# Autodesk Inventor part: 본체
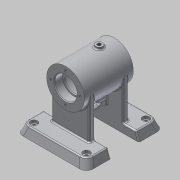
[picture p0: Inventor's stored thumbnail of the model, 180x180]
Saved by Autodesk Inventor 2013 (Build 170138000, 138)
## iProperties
Created: 2016-07
Part Number: 본체
Material: 알루미늄 6061
Document SubType Name: Modeling
Designer: Administrator
Density: 2.71 g/cm^3
Mass: 500.66 g
Surface Area: 530.533 cm^2
Volume: 184.745 cm^3
Author: Administrator
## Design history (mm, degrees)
sketch "스케치2"
  geometry: L1 (0, 0)-(70, 0); L2 (0, 27)-(70, 27); L3 (0, 27)-(0, 16); L4 (0, 16)-(12, 16); L5 (12, 16)-(12, 14); L6 (12, 14)-(14, 14); L7 (14, 14)-(14, 22); L8 (14, 22)-(56, 22); L9 (56, 22)-(56, 14); L10 (56, 14)-(58, 14); L11 (58, 14)-(58, 16); L12 (58, 16)-(70, 16); L13 (70, 16)-(70, 27)
  constraints: 26 end point, 6 parallel, 6 perpendicular, 1 horizontal, 1 vertical
  dimensions: "d0" = 0 distance from line of L3 L1.start; "d1" = 32 diameter of L4 L1; "d2" = 12 distance between parallel lines of L5 L3; "d3" = 54 diameter of L2 L1; "d4" = 28 diameter of L6 L1; "d5" = 42 distance between parallel lines of L9 L7; "d6" = 44 diameter of L8 L1; "d7" = 2 distance of L5.end L6.end; "d8" = 70 distance of L2.start L2.end; "d9" = 32 diameter of L12 L1; "d10" = 2 distance of L9.end L10.end; "d11" = 28 diameter of L10 L1
revolve "회전1" sketch "스케치2" stored, may be unused: angle "d12" = 90 deg
node "작업 평면1"
sketch "스케치3"
  geometry: L1 (27, 70)-(-27, 70) reference; L2 (27, 0)-(-27, 0) reference; L3 (27, 0)-(-27, 0) reference; L4 (-25.21, 35)-(27.411, 35); L5 (-50, 90)-(50, 90); L6 (50, 90)-(50, 55); L7 (50, 55)-(-50, 55); L8 (-50, 55)-(-50, 90); L9 (0, 70)-(0, 0); L10 (-50, 15)-(50, 15); L11 (50, 15)-(50, -20); L12 (50, -20)-(-50, -20); L13 (-50, -20)-(-50, 15); L14 (-4, 55)-(-4, 15); L15 (4, 15)-(4, 55)
  constraints: 24 end point, 6 parallel, 4 perpendicular, 4 point on line, 2 horizontal, 1 midpoint
  dimensions: "d14" = 35 distance between parallel lines of L4 L1; "d16" = 100 distance between parallel lines of L6 L8; "d18" = 50 distance between parallel lines of L9 L8; "d19" = 35 distance between parallel lines of L5 L7; "d20" = 55 distance between parallel lines of L4 L5; "d21" = 55 distance between parallel lines of L12 L4; "d22" = 35 distance between parallel lines of L12 L10; "d23" = 100 distance between parallel lines of L13 L11; "d24" = 50 distance between parallel lines of L9 L13; "d25" = 8 distance between parallel lines of L15 L14; "d26" = 4 distance between parallel lines of L9 L14 (= 0.5 x d25)
extrude "돌출1" join sketch "스케치3" distance "d27" = 12; taper "d28" = 0 deg
sketch "스케치4"
  geometry: L1 (0, 0)-(100, 0) reference; L2 (100, 0)-(100, 12) reference; L3 (0, 12)-(100, 12) reference; L4 (0, 0)-(0, 12) reference; L5 (95.632, 12)-(100, 0); L6 (4.368, 12)-(0, 0); 1 further point
  constraints: 4 end point, 2 point on line
  dimensions: "d29" = 110 deg angle of L1 L5; "d30" = 110 deg angle of L1 L6
extrude "돌출2" cut sketch "스케치4" stored distance "d31" = 12; taper "d32" = 0 deg
node "작업 평면2"
sketch "스케치5"
  geometry: L1 (15, -58)-(15, -70) reference; L2 (-20, -58)-(15, -58) reference; L3 (-20, -70)-(-20, -58) reference; L4 (-20, -70)-(15, -70) reference; L5 (55, -70)-(55, -58) reference; L6 (55, -70)-(90, -70) reference; L7 (90, -58)-(90, -70) reference; L8 (55, -58)-(90, -58) reference; L9 (-20, -70)-(-15.632, -58); L10 (90, -70)-(85.632, -58); 1 further point
  constraints: 4 end point, 2 point on line
  dimensions: "d34" = 110 deg angle of L4 L9; "d35" = 110 deg angle of L6 L10
extrude "돌출3" cut sketch "스케치5" stored distance "d36" = 12; taper "d37" = 0 deg
sketch "스케치6"
  geometry: L1 (45.632, 15)-(4, 15) reference; L2 (4, 55)-(45.632, 55) reference; L3 (-45.632, 55)-(-4, 55) reference; L4 (-4, 55)-(-4, 15) reference; L5 (-4, 15)-(-45.632, 15) reference; L6 (27, 15)-(27, 7); L7 (27, 7)-(-27, 7); L8 (-27, 7)-(-27, 15); L9 (27, 55)-(27, 63); L10 (27, 63)-(-27, 63); L11 (-27, 63)-(-27, 55); L12 (0, 15)-(0, 55); L13 (-4, 15)-(-4, 55); L14 (4, 55)-(4, 15); L15 (-27, 15)-(-4, 15); L16 (4, 15)-(27, 15); L17 (4, 55)-(27, 55); L18 (-4, 55)-(-27, 55); 1 further point
  constraints: 26 end point, 5 collinear, 2 parallel, 2 point on line, 1 perpendicular
  dimensions: "d42" = 54 distance between parallel lines of L6 L8; "d48" = 54 distance between parallel lines of L9 L11; "d49" = 4 distance between parallel lines of L12 L4; "d50" = 27 distance from line of point (0, 0) L8; "d51" = 27 distance between parallel lines of L12 L11; "d52" = 8 distance between parallel lines of L2 L10; "d54" = 8 distance between parallel lines of L15 L7; "d55" = 8 distance of L6.start L6.end; "d56" = 0 distance from line of L15 L12.start; "d57" = 0 distance from line of L12.end L3
extrude "돌출4" join sketch "스케치6" stored distance "d58" = 12; taper "d59" = 0 deg
sketch "스케치7"
  geometry: L1 (0, 0)-(0, 40) reference; L2 (-22.298, 0)-(-22.298, 40); L3 (-43.298, 0)-(-43.298, 40) reference; L4 (-22.298, 0)-(0, 0); L5 (0, 40)-(-22.298, 40); L6 (0, 40)-(0, 0); 1 further point
  constraints: 8 end point, 2 equal length, 1 perpendicular
  dimensions: "d62" = 21 distance between parallel lines of L2 L3
extrude "돌출5" cut sketch "스케치7" stored distance "d63" = 12; taper "d64" = 0 deg
sketch "스케치8"
  geometry: L1 (21, 0)-(21, 40) reference; L2 (0, 0)-(0, 40) reference; L3 (21, 0)-(0, 0) reference; L4 (11.298, 8.5)-(11.298, 31.5); L5 (43.298, 40)-(43.298, 75) reference; L6 (0, 20)-(21, 20); L7 (0.298, -15)-(-53.702, -15) reference; L8 (7.798, 12)-(7.798, 28); L9 (14.798, 12)-(14.798, 28); A1 r 3.5 centre (11.298, 12) between (7.798, 12) and (14.798, 12); A2 r 3.5 centre (11.298, 28) between (14.798, 28) and (7.798, 28); 1 further point
  constraints: 8 end point, 4 point on circle, 4 tangent, 2 centre point, 2 midpoint, 2 perpendicular, 2 point on line
  dimensions: "d65" = 7 diameter of A1; "d67" = 7 diameter of A2; "d69" = 32 distance between parallel lines of L5 L4; "d70" = 35 distance between parallel lines of L6 L7; "d71" = 23 distance of L4.start L4.end; "d72" = 11.5 distance from line of L6 L4.start (= 0.5 x d71); "d73" = 23 dimension on A2 A1; "d74" = 11.5 dimension on A1 L6
extrude "돌출6" cut sketch "스케치8" stored distance "d75" = 12; taper "d76" = 0 deg
node "작업 평면3"
sketch "스케치9"
  geometry: L1 (0, 0)-(15.898, -25.441); L2 (0, 0)-(0, -14)
  constraints: 4 end point, 1 vertical, 1 vertical alignment, 1 other
  dimensions: "d78" = 30 distance of L1.start L1.end; "d79" = 32 deg angle of L2 L1
node "작업 평면4"
sketch "스케치10"
  geometry: L1 (-8, -14.89)-(8, -14.89) reference; L2 (-20, 7.963)-(-20, -7.838) reference; C1 r 6 at (0, 0.063); 3 further points
  constraints: 2 midpoint, 1 centre point, 1 horizontal alignment, 1 vertical alignment
  dimensions: "d80" = 12 diameter of C1
extrude "돌출7" join sketch "스케치10" stored distance "d82" = 12; taper "d83" = 0 deg
node "작업 평면6"
sketch "스케치11"
  geometry: L1 (27, 70)-(-27, 70) reference; C1 r 5 at (0, 48); 1 further point
  constraints: 1 centre point, 1 vertical alignment
  dimensions: "d85" = 10 diameter of C1; "d87" = 22 distance from line of L1 C1.centre
extrude "돌출8" join sketch "스케치11" stored distance "d88" = 12; taper "d89" = 0 deg
sketch "스케치12"
  geometry: L1 (-27, 55)-(-27, 63) reference; L2 (-27, 63)-(27, 63) reference; L3 (27, 63)-(27, 55) reference; L4 (27, 55)-(45.632, 55) reference; L5 (45.632, 55)-(45.632, 85.632) reference; L6 (45.632, 85.632)-(-45.632, 85.632) reference; L7 (-45.632, 85.632)-(-45.632, 55) reference; L8 (-45.632, 55)-(-27, 55) reference; L9 (-50, 15)-(-50, -20) reference; L10 (-50, -20)-(50, -20) reference; C1 r 5 at (-37.5, -7.5); 1 further point
  constraints: 1 centre point
  dimensions: "d90" = 10 diameter of C1; "d92" = 12.5 distance from line of L9 C1.centre; "d93" = 12.5 distance from line of L10 C1.centre
extrude "돌출9" cut sketch "스케치12" distance "d94" = 4; taper "d95" = 0 deg
sketch "스케치13"
  geometry: C1 r 5 at (0, 0) reference; C2 r 3 at (0, 0); 1 further point
  constraints: 1 centre point, 1 coincident
  dimensions: "d96" = 6 diameter of C2
extrude "돌출10" cut sketch "스케치13" stored distance "d98" = 4; taper "d99" = 0 deg
fillet "모깎기1" dims "d106" = 10
fillet "모깎기2" dims "d107" = 2
fillet "모깎기3" dims "d108" = 2
fillet "모깎기4" dims "d109" = 2
chamfer "모따기1" distance "d110" = 1; stored, may be unused: second distance "d111" = 2, angle "d112" = 110 deg
fillet "모깎기5" dims "d113" = 0.3
fillet "모깎기6" dims "d114" = 3
fillet "모깎기7" dims "d115" = 2
fillet "모깎기8" dims "d116" = 2
fillet "모깎기9" dims "d117" = 2
fillet "모깎기10" dims "d118" = 2
fillet "모깎기11" dims "d119" = 2
sketch "스케치14"
  geometry: C1 r 6 at (0, 0) reference; C2 r 3 at (0, 0); 1 further point
  constraints: 1 centre point, 1 coincident
  dimensions: "d120" = 6 diameter of C2
hole "구멍1" sketch "스케치14" at (0, 0) diameter "d122" = 5.188; stored, may be unused: countersink angle "d126" = 90 deg, drill point angle "d128" = 118 deg; dims "d123" = 6, "d124" = 4, "d125" = 2, "d127" = 8
sketch "스케치15"
  geometry: C1 r 5 at (0, 0) reference; C2 r 3 at (0, 0); 1 further point
  constraints: 1 centre point, 1 coincident
  dimensions: "d129" = 6 diameter of C2
hole "구멍2" sketch "스케치15" at (0, 0) diameter "d131" = 5.188; stored, may be unused: countersink angle "d135" = 90 deg, drill point angle "d137" = 118 deg; dims "d132" = 6, "d133" = 4, "d134" = 2, "d136" = 8
node "작업 평면7"
sketch "스케치16"
  geometry: L1 (-20.739, 1.26)-(20.739, 1.26); L2 (20.739, 1.26)-(20.739, -1.26); L3 (20.739, -1.26)-(-20.739, -1.26); L4 (-20.739, -1.26)-(-20.739, 1.26); L5 (-20.739, 0)-(20.739, 0); L6 (0, 1.26)-(0, -1.26); L7 (8, -32.5)-(-8, -32.5) reference; 3 further points
  constraints: 6 midpoint, 4 end point, 1 horizontal, 1 vertical alignment, 2 other
  dimensions: "d138" = 0 distance from line of point (35, 0) L5
feature "엠보싱1" sketch "스케치16" dims "d139" = 0.5, "d140" = 0
sketch "스케치17" dims "d141" = 42
  geometry: C1 r 27 at (0, 0) reference; C2 r 17 at (0, 0) reference; C3 r 2 at (0, 21); 1 further point
  constraints: 2 vertical alignment, 1 centre point, 1 coincident, 2 other
  dimensions: "d143" = 4 diameter of C3
hole "구멍3" sketch "스케치17" at (0, 21) diameter "d144" = 3.242; stored, may be unused: countersink angle "d148" = 82 deg, drill point angle "d150" = 118 deg; dims "d145" = 8, "d146" = 3.023, "d147" = 2, "d149" = 10
sketch "스케치18" dims "d154" = 42
  geometry: C1 r 27 at (0, 0) reference; C2 r 17 at (0, 0) reference; C3 r 2 at (0, -21); 1 further point
  constraints: 2 vertical alignment, 1 centre point, 1 coincident, 2 other
  dimensions: "d156" = 4 diameter of C3
hole "구멍4" sketch "스케치18" at (0, -21) diameter "d157" = 3.242; stored, may be unused: countersink angle "d161" = 82 deg, drill point angle "d163" = 118 deg; dims "d158" = 8, "d159" = 3.023, "d160" = 2, "d162" = 10
node "솔리드1"
pattern_linear "직사각형 패턴1" dims "d102" = 85, "d105" = 75
pattern_circular "원형 패턴1" dims angle "d152" = 360 deg
pattern_circular "원형 패턴2" dims angle "d165" = 360 deg
node "투영된 루프1"
node "투영된 루프2"
node "투영된 루프3"
node "투영된 루프4"
other parameters: "d77" = 35
